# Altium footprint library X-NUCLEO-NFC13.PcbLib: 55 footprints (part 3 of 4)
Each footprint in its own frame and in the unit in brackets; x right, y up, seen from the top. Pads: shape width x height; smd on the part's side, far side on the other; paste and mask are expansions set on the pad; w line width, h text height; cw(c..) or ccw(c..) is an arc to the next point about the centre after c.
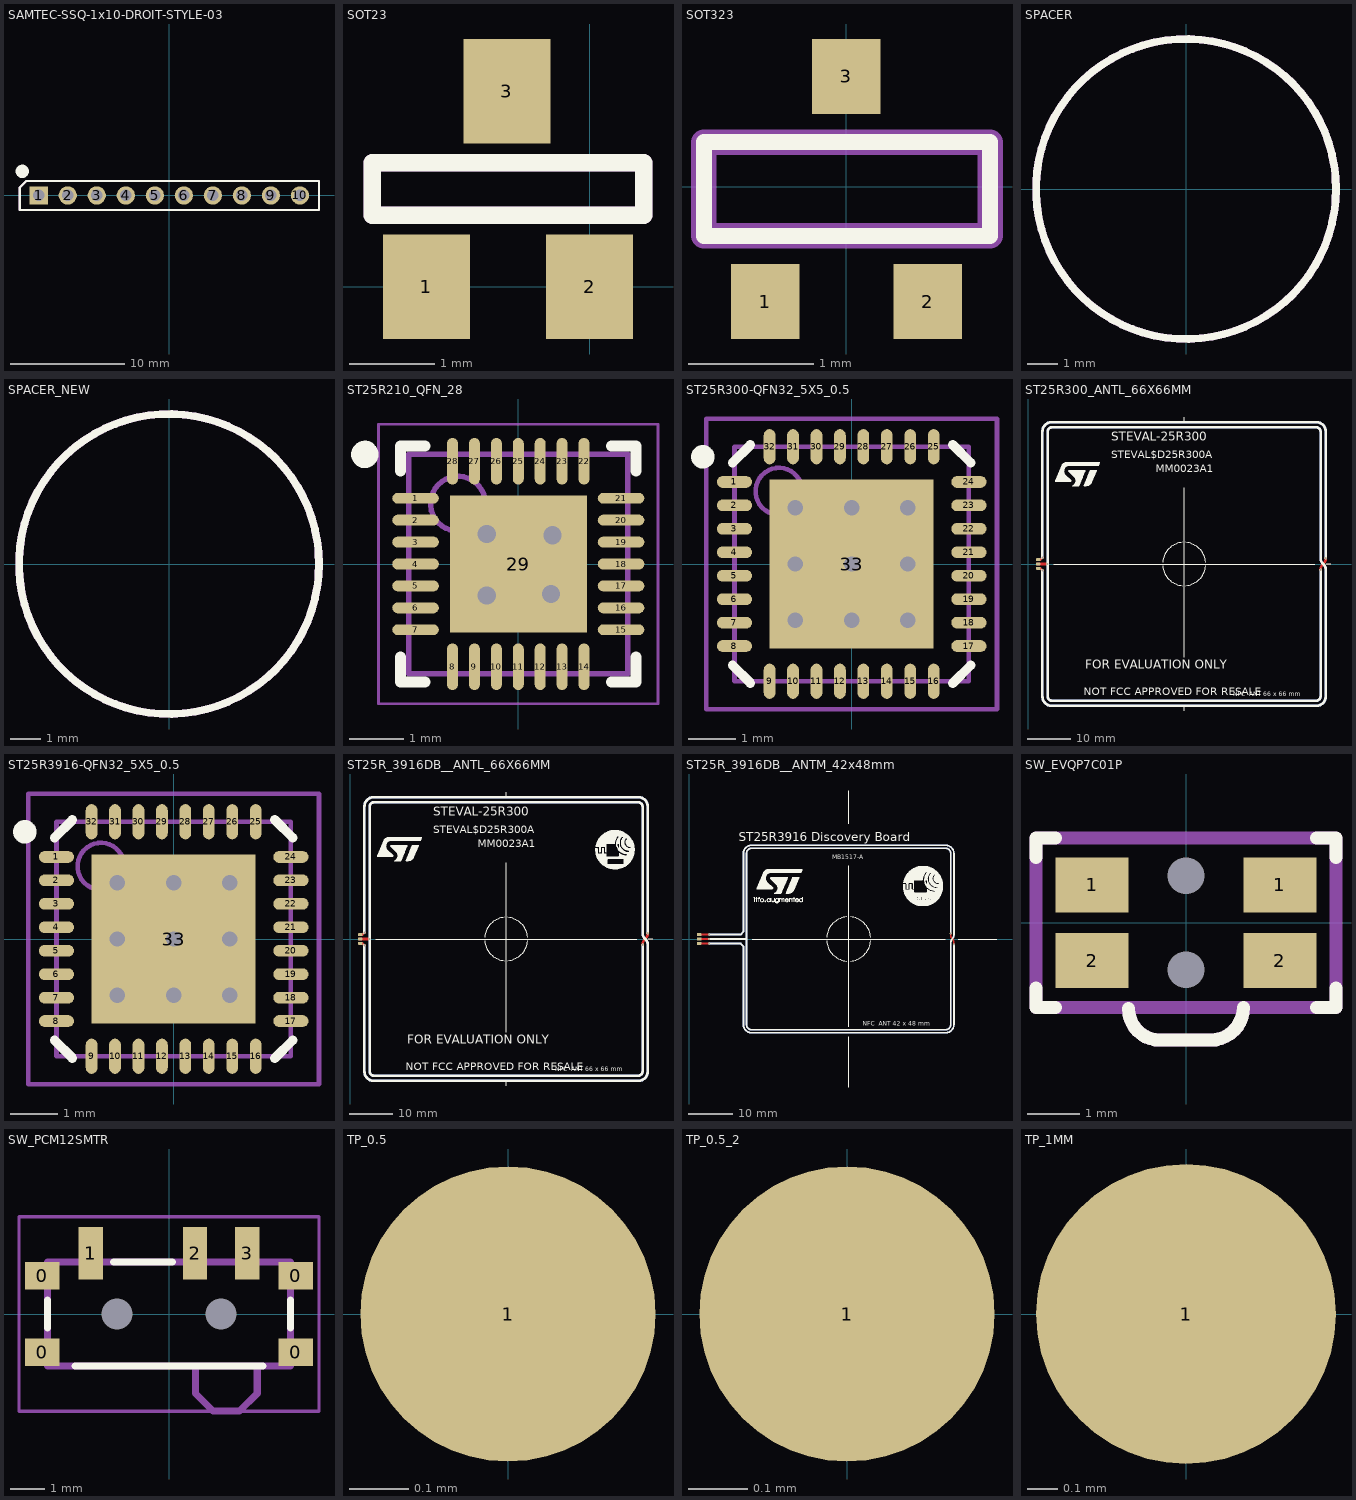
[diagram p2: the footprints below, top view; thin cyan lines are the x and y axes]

## SAMTEC-SSQ-1x10-DROIT-STYLE-03 [mm]
pads (10):
  rect 1.6x1.6 hole 1: 1(-11.43,0)
  round 1.6 hole 1: 2(-8.89,0) 3(-6.35,0) 4(-3.81,0) 5(-1.27,0) 6(1.27,0) 7(3.81,0) 8(6.35,0) 9(8.89,0) 10(11.43,0)
Top Overlay:
  circle w0.6: c-12.874,2.11 r0.284
  lines w0.2: -13.1,-1.27 13.1,-1.27 13.1,1.27 -12.53,1.27 -13.1,0.7 -13.1,-1.27
Top Assembly:
  lines w0.2: -13.1,-1.27 13.1,-1.27 13.1,1.27 -12.53,1.27 -13.1,0.7 -13.1,-1.27
  text "1" at -11.274,0.46 h1.05
  text ".Designator" at 3.976,2.71 h1.05
3D body "SSQ-110-03-L-S.stp": height 8.51, standoff -10.01, extent -12.954,-1.207 12.954,1.206

## SOT23 [mil]
pads (3):
  rect 40x48 smd paste+0 mask+0: 1(-75,0) 2(0,0) 3(-38,90)
Top Overlay:
  lines w8: -100,32.87 25,32.87 25,57.13 -100,57.13 -100,32.87
Top Assembly:
  lines w8: -100,32.87 25,32.87 25,57.13 -100,57.13 -100,32.87
  text ".Designator" at -105.54,66.46 h23.62
3D body: height 7.87, standoff 0, extent -45.28,62.99 -29.53,106.3
3D body: height 7.87, standoff 0, extent -82.68,-15.75 -66.93,27.56
3D body: height 7.87, standoff 0, extent -7.87,-15.75 7.87,27.56
3D body: height 15.75, standoff 1.97, extent -98.43,27.56 23.62,62.99

## SOT323 [mm]
pads (3):
  rect 0.55x0.6 smd paste+0 mask+0: 1(-0.65,-0.919) 2(0.65,-0.919) 3(0,0.881)
Top Overlay:
  lines w0.127: -1.14,-0.394 1.15,-0.394 1.15,0.356 -1.14,0.356 -1.14,-0.394
Top Assembly:
  lines w0.203: -1.14,-0.394 1.15,-0.394 1.15,0.356 -1.14,0.356 -1.14,-0.394
  text ".Designator" at -1.431,0.688 h0.6
3D body: height 0.2, standoff 0, extent -0.15,0.381 0.15,1.131
3D body: height 0.2, standoff 0, extent 0.45,-1.169 0.85,-0.419
3D body: height 0.2, standoff 0, extent -0.85,-1.169 -0.45,-0.394
3D body: height 0.4, standoff 0.05, extent -1.1,-0.494 1.05,0.406

## SPACER [mm] "spacer d5mmx4mm"
height 4
Top Overlay:
  circle w0.254: c0,0 r5
Top Assembly:
  circle w0.254: c0,0 r5
  text ".Designator" at -2.703,-0.326 h0.6

## SPACER_NEW [mm] "spacer d5mmx4mm"
height 4
Top Overlay:
  circle w0.254: c0,0 r5
Top Assembly:
  circle w0.254: c0,0 r5
  text ".Designator" at -2.703,-0.326 h0.6
3D body "SJxx03.stp": height 5.08, standoff 0, extent -5.561,-5.535 5.603,5.635

## ST25R210_QFN_28 [mm] "QFN, 28-Leads, Body 3,95x3,95mm, Pitch 0,40mm, Thermal Pad 2,50x2,50mm, IPC Medium Density"
height 0.55
pads (29):
  oval 0.85x0.2 smd: 1(-1.875,1.2) 2(-1.875,0.8) 3(-1.875,0.4) 4(-1.875,0) 5(-1.875,-0.4) 6(-1.875,-0.8) 7(-1.875,-1.2) 15(1.875,-1.2) 16(1.875,-0.8) 17(1.875,-0.4) 18(1.875,0) 19(1.875,0.4) 20(1.875,0.8) 21(1.875,1.2)
  oval 0.2x0.85 smd: 8(-1.2,-1.875) 9(-0.8,-1.875) 10(-0.4,-1.875) 11(0,-1.875) 12(0.4,-1.875) 13(0.8,-1.875) 14(1.2,-1.875) 22(1.2,1.875) 23(0.8,1.875) 24(0.4,1.875) 25(0,1.875) 26(-0.4,1.875) 27(-0.8,1.875) 28(-1.2,1.875)
  rect 2.5x2.5 smd: 29(0,0)
via -0.575,-0.575 diameter 0.66 hole 0.33
via 0.6,-0.55 diameter 0.66 hole 0.33
via 0.625,0.525 diameter 0.66 hole 0.33
via -0.575,0.55 diameter 0.66 hole 0.33
Top Overlay:
  circle w0.25: c-2.8,2 r0.125
  lines w0.2: -2.15,-1.7 -2.15,-2.15 -1.7,-2.15 ; -2.15,1.7 -2.15,2.15 -1.7,2.15 ; 1.7,-2.15 2.15,-2.15 2.15,-1.7 ; 1.7,2.15 2.15,2.15 2.15,1.7
Top Assembly:
  circle w0.1: c-1.1,1.1 r0.5
  lines w0.1: -2,-2 2,-2 2,2 -2,2 -2,-2
Top Courtyard:
  lines w0.05: -2.55,-2.55 2.55,-2.55 2.55,2.55 -2.55,2.55 -2.55,-2.55
  lines w0.1: -0.5,0 0.5,0 ; 0,-0.5 0,0.5
3D body "QFN40P395X395X55_HS-29N.step": height 0.55, standoff 0, extent -2.01,-2.01 2.01,2.01

## ST25R300-QFN32_5X5_0.5 [mm]
height 0.5
pads (33):
  oval 0.75x0.25 smd mask+0.05: 1(-2.5,1.75) 2(-2.5,1.25) 3(-2.5,0.75) 4(-2.5,0.25) 5(-2.5,-0.25) 6(-2.5,-0.75) 7(-2.5,-1.25) 8(-2.5,-1.75) 17(2.5,-1.75) 18(2.5,-1.25) 19(2.5,-0.75) 20(2.5,-0.25) 21(2.5,0.25) 22(2.5,0.75) 23(2.5,1.25) 24(2.5,1.75)
  oval 0.25x0.75 smd mask+0.05: 9(-1.75,-2.5) 10(-1.25,-2.5) 11(-0.75,-2.5) 12(-0.25,-2.5) 13(0.25,-2.5) 14(0.75,-2.5) 15(1.25,-2.5) 16(1.75,-2.5) 25(1.75,2.5) 26(1.25,2.5) 27(0.75,2.5) 28(0.25,2.5) 29(-0.25,2.5) 30(-0.75,2.5) 31(-1.25,2.5) 32(-1.75,2.5)
  rect 3.5x3.6 smd paste-10 mask+0.05: 33(0,0)
via -1.2,-1.2 diameter 0.66 hole 0.33
via 1.2,-1.2 diameter 0.66 hole 0.33
via 0,-1.2 diameter 0.66 hole 0.33
via 1.2,0 diameter 0.66 hole 0.33
via 0,0 diameter 0.66 hole 0.33
via -1.2,0 diameter 0.66 hole 0.33
via 1.2,1.2 diameter 0.66 hole 0.33
via 0,1.2 diameter 0.66 hole 0.33
via -1.2,1.2 diameter 0.66 hole 0.33
Top Overlay:
  circle w0.25: c-3.173,2.286 r0.125
  lines w0.2: -2.54,-2.159 -2.159,-2.54 ; -2.54,2.159 -2.159,2.54 ; 2.159,-2.54 2.54,-2.159 ; 2.159,2.54 2.54,2.159
Top Paste:
  rectangle: -1.016,0.179 -0.178,1.017
  rectangle: 0.177,0.178 1.015,1.016
  rectangle: 0.178,-1.017 1.016,-0.179
  rectangle: -1.016,-1.015 -0.178,-0.177
  rectangle: 0.179,1.372 1.017,1.753
  rectangle: -1.015,1.372 -0.177,1.753
  rectangle: -1.04,-1.753 -0.202,-1.372
  rectangle: 0.179,-1.753 1.017,-1.372
  region: 1.727,0.179 1.727,1.017 1.346,1.017 1.346,0.179
  region: 1.726,-1.016 1.726,-0.178 1.345,-0.178 1.345,-1.016
  region: -1.346,-1.015 -1.346,-0.177 -1.727,-0.177 -1.727,-1.015
  region: -1.346,0.179 -1.346,1.017 -1.727,1.017 -1.727,0.179
Top Assembly:
  circle w0.1: c-1.55,1.55 r0.5
  lines w0.1: -2.5,-2.5 2.5,-2.5 2.5,2.5 -2.5,2.5 -2.5,-2.5
  text ".Designator" at -2.203,-1.326 h0.6
Top Courtyard:
  lines w0.1: -0.5,0 0.5,0 ; 0,-0.5 0,0.5 ; -3.1,-3.1 3.1,-3.1 3.1,3.1 -3.1,3.1 -3.1,-3.1
3D body "ST25R3916-QFN32-5.STEP": height 0.85, standoff 0, extent -2.501,-2.501 2.501,2.501

## ST25R300_ANTL_66X66MM [mm] "66mm x 66mm"
pads (3):
  rrect50% 1x0.7 smd: 1(2.275,-1) 2(2.275,1) 3(2.275,0)
via 68.65,1.334 diameter 0.6 hole 0.3
via 67.45,-1.334 diameter 0.6 hole 0.3
via 4.45,0 diameter 0.5 hole 0.2
via 3.25,1.45 diameter 0.5 hole 0.2
via 3.25,-1.45 diameter 0.5 hole 0.2
Top Layer:
  lines w0.6: 2.275,-1 2.8,-1 3.25,-1.45 ; 2.275,0 4.45,0 ; 2.275,1 2.8,1 3.25,1.45 ; 67.45,-1.334 cw(c69.223,-1.334) 67.969,-0.081 68.131,0.081 ccw(c66.877,1.334) 68.65,1.334
Bottom Layer:
  lines w0.6: 3.25,-1.45 3.25,-30.525 ccw(c5.475,-30.525) 5.475,-32.75 ; 3.25,1.45 3.25,30.525 cw(c5.475,30.525) 5.475,32.75 ; 67.45,-1.334 cw(c67.445,-1.339) 67.452,-1.339 67.452,-30.526 cw(c66.428,-30.526) 66.428,-31.55 5.474,-31.55 cw(c5.474,-30.526) 4.45,-30.526 4.45,30.526 cw(c5.474,30.526) 5.474,31.55 66.428,31.55 cw(c66.428,30.526) 67.452,30.526 67.452,1.334 ccw(c69.23,1.334) 67.973,0.077 68.131,-0.081 cw(c66.877,-1.334) 68.65,-1.334 68.65,-30.525 ; 68.65,1.334 68.65,30.525 ; 68.652,-30.525 cw(c66.427,-30.525) 66.427,-32.75 5.475,-32.75 ; 68.652,30.525 ccw(c66.427,30.525) 66.427,32.75 5.475,32.75 ; 5.475,-32.75 5.475,-32.75 ; 5.475,32.75 5.475,32.75
Top Overlay:
  drawing of 419 lines, arcs and shapes, not listed
  text "STEVAL-25R300" at 19.123,27.726 h3.5
  text "NFC  ANT 66 x 66 mm" at 47.275,-30.5 h1
  text "MM0023A1" at 29.402,20.585 h3
  text "STEVAL$D25R300A" at 19.133,23.821 h3
  text "FOR EVALUATION ONLY" at 13.147,-24.825 h3.5
  text "NOT FCC APPROVED FOR RESALE" at 12.829,-30.871 h3
Bottom Overlay:
  lines w0.2: 5.85,0 66.05,0 ; 30.969,-0.436 ccw(c35.95,0) 35.514,-4.981 ; 30.969,0.436 cw(c35.95,0) 35.514,4.981 ; 35.929,-21.525 35.949,17.57 ; 35.95,-33.85 35.95,-32.825 ; 35.95,32.825 35.95,33.85 ; 36.386,-4.981 ccw(c35.95,0) 40.931,-0.436 ; 36.386,4.981 cw(c35.95,0) 40.931,0.436 ; 68.725,0.05 69.75,0.05
  lines w0.6: 3.25,-1.45 3.25,-30.525 ccw(c5.475,-30.525) 5.475,-32.75 ; 3.25,1.45 3.25,30.525 cw(c5.475,30.525) 5.475,32.75 ; 67.45,-1.334 cw(c67.445,-1.339) 67.452,-1.339 67.452,-30.526 cw(c66.428,-30.526) 66.428,-31.55 5.474,-31.55 cw(c5.474,-30.526) 4.45,-30.526 4.45,30.526 cw(c5.474,30.526) 5.474,31.55 66.428,31.55 cw(c66.428,30.526) 67.452,30.526 67.452,1.334 ccw(c69.23,1.334) 67.973,0.077 68.131,-0.081 cw(c66.877,-1.334) 68.65,-1.334 68.65,-30.525 ; 68.65,1.334 68.65,30.525 ; 68.652,-30.525 cw(c66.427,-30.525) 66.427,-32.75 5.475,-32.75 ; 68.652,30.525 ccw(c66.427,30.525) 66.427,32.75 5.475,32.75 ; 5.475,-32.75 5.475,-32.75 ; 5.475,32.75 5.475,32.75 ; 3.25,2 ccw(c3.25,2) 3.25,2

## ST25R3916-QFN32_5X5_0.5 [mm]
height 0.5
pads (33):
  oval 0.75x0.25 smd mask+0.05: 1(-2.5,1.75) 2(-2.5,1.25) 3(-2.5,0.75) 4(-2.5,0.25) 5(-2.5,-0.25) 6(-2.5,-0.75) 7(-2.5,-1.25) 8(-2.5,-1.75) 17(2.5,-1.75) 18(2.5,-1.25) 19(2.5,-0.75) 20(2.5,-0.25) 21(2.5,0.25) 22(2.5,0.75) 23(2.5,1.25) 24(2.5,1.75)
  oval 0.25x0.75 smd mask+0.05: 9(-1.75,-2.5) 10(-1.25,-2.5) 11(-0.75,-2.5) 12(-0.25,-2.5) 13(0.25,-2.5) 14(0.75,-2.5) 15(1.25,-2.5) 16(1.75,-2.5) 25(1.75,2.5) 26(1.25,2.5) 27(0.75,2.5) 28(0.25,2.5) 29(-0.25,2.5) 30(-0.75,2.5) 31(-1.25,2.5) 32(-1.75,2.5)
  rect 3.5x3.6 smd paste-10 mask+0.05: 33(0,0)
via -1.2,1.2 diameter 0.66 hole 0.33
via 0,1.2 diameter 0.66 hole 0.33
via 1.2,1.2 diameter 0.66 hole 0.33
via -1.2,0 diameter 0.66 hole 0.33
via 0,0 diameter 0.66 hole 0.33
via 1.2,0 diameter 0.66 hole 0.33
via 0,-1.2 diameter 0.66 hole 0.33
via 1.2,-1.2 diameter 0.66 hole 0.33
via -1.2,-1.2 diameter 0.66 hole 0.33
Top Overlay:
  circle w0.25: c-3.173,2.286 r0.125
  lines w0.2: -2.54,-2.159 -2.159,-2.54 ; -2.54,2.159 -2.159,2.54 ; 2.159,-2.54 2.54,-2.159 ; 2.159,2.54 2.54,2.159
Top Paste:
  region: -1.346,0.179 -1.346,1.017 -1.727,1.017 -1.727,0.179
  region: -1.346,-1.015 -1.346,-0.177 -1.727,-0.177 -1.727,-1.015
  region: 1.726,-1.016 1.726,-0.178 1.345,-0.178 1.345,-1.016
  region: 1.727,0.179 1.727,1.017 1.346,1.017 1.346,0.179
  rectangle: 0.179,-1.753 1.017,-1.372
  rectangle: -1.04,-1.753 -0.202,-1.372
  rectangle: -1.015,1.372 -0.177,1.753
  rectangle: 0.179,1.372 1.017,1.753
  rectangle: -1.016,-1.015 -0.178,-0.177
  rectangle: 0.178,-1.017 1.016,-0.179
  rectangle: 0.177,0.178 1.015,1.016
  rectangle: -1.016,0.179 -0.178,1.017
Top Assembly:
  circle w0.1: c-1.55,1.55 r0.5
  lines w0.1: -2.5,-2.5 -2.5,2.5 2.5,2.5 2.5,-2.5 -2.5,-2.5
  text ".Designator" at -2.203,-1.326 h0.6
Top Courtyard:
  lines w0.1: -0.5,0 0.5,0 ; 0,-0.5 0,0.5 ; -3.1,-3.1 -3.1,3.1 3.1,3.1 3.1,-3.1 -3.1,-3.1
3D body "ST25R3916-QFN32-5.STEP": height 0.85, standoff 0, extent -2.501,-2.501 2.501,2.501

## ST25R_3916DB__ANTL_66X66MM [mm] "66mm x 66mm"
pads (3):
  rrect50% 1x0.7 smd: 1(2.275,-1) 2(2.275,1) 3(2.275,0)
via 3.25,-1.45 diameter 0.5 hole 0.2
via 3.25,1.45 diameter 0.5 hole 0.2
via 4.45,0 diameter 0.5 hole 0.2
via 67.45,-1.334 diameter 0.6 hole 0.3
via 68.65,1.334 diameter 0.6 hole 0.3
Top Layer:
  lines w0.6: 2.275,-1 2.8,-1 3.25,-1.45 ; 2.275,0 4.45,0 ; 2.275,1 2.8,1 3.25,1.45 ; 67.45,-1.334 cw(c69.223,-1.334) 67.969,-0.081 68.131,0.081 ccw(c66.877,1.334) 68.65,1.334
Bottom Layer:
  lines w0.6: 3.25,-1.45 3.25,-30.525 ccw(c5.475,-30.525) 5.475,-32.75 ; 3.25,1.45 3.25,30.525 cw(c5.475,30.525) 5.475,32.75 ; 67.45,-1.334 cw(c67.445,-1.339) 67.452,-1.339 67.452,-30.526 cw(c66.428,-30.526) 66.428,-31.55 5.474,-31.55 cw(c5.474,-30.526) 4.45,-30.526 4.45,30.526 cw(c5.474,30.526) 5.474,31.55 66.428,31.55 cw(c66.428,30.526) 67.452,30.526 67.452,1.334 ccw(c69.23,1.334) 67.973,0.077 68.131,-0.081 cw(c66.877,-1.334) 68.65,-1.334 68.65,-30.525 ; 68.65,1.334 68.65,30.525 ; 68.652,-30.525 cw(c66.427,-30.525) 66.427,-32.75 5.475,-32.75 ; 68.652,30.525 ccw(c66.427,30.525) 66.427,32.75 5.475,32.75 ; 5.475,-32.75 5.475,-32.75 ; 5.475,32.75 5.475,32.75
Top Overlay:
  drawing of 426 lines, arcs and shapes, not listed
  text "NOT FCC APPROVED FOR RESALE" at 12.829,-30.871 h3
  text "FOR EVALUATION ONLY" at 13.147,-24.825 h3.5
  text "STEVAL$D25R300A" at 19.133,23.821 h3
  text "MM0023A1" at 29.402,20.585 h3
  text "NFC  ANT 66 x 66 mm" at 47.275,-30.5 h1
  text "STEVAL-25R300" at 19.123,27.726 h3.5
Bottom Overlay:
  lines w0.2: 5.85,0 66.05,0 ; 30.969,-0.436 ccw(c35.95,0) 35.514,-4.981 ; 30.969,0.436 cw(c35.95,0) 35.514,4.981 ; 35.929,-21.525 35.949,17.57 ; 35.95,-33.85 35.95,-32.825 ; 35.95,32.825 35.95,33.85 ; 36.386,-4.981 ccw(c35.95,0) 40.931,-0.436 ; 36.386,4.981 cw(c35.95,0) 40.931,0.436 ; 68.725,0.05 69.75,0.05
  lines w0.6: 3.25,-1.45 3.25,-30.525 ccw(c5.475,-30.525) 5.475,-32.75 ; 3.25,1.45 3.25,30.525 cw(c5.475,30.525) 5.475,32.75 ; 67.45,-1.334 cw(c67.445,-1.339) 67.452,-1.339 67.452,-30.526 cw(c66.428,-30.526) 66.428,-31.55 5.474,-31.55 cw(c5.474,-30.526) 4.45,-30.526 4.45,30.526 cw(c5.474,30.526) 5.474,31.55 66.428,31.55 cw(c66.428,30.526) 67.452,30.526 67.452,1.334 ccw(c69.23,1.334) 67.973,0.077 68.131,-0.081 cw(c66.877,-1.334) 68.65,-1.334 68.65,-30.525 ; 68.65,1.334 68.65,30.525 ; 68.652,-30.525 cw(c66.427,-30.525) 66.427,-32.75 5.475,-32.75 ; 68.652,30.525 ccw(c66.427,30.525) 66.427,32.75 5.475,32.75 ; 5.475,-32.75 5.475,-32.75 ; 5.475,32.75 5.475,32.75 ; 3.25,2 ccw(c3.25,2) 3.25,2

## ST25R_3916DB__ANTM_42x48mm [mm] "42mm x 48mm"
pads (3):
  rrect50% 1x0.7 smd: 1(2.275,-1) 2(2.275,1) 3(2.275,0)
via 4.45,1 diameter 0.5 hole 0.2
via 4.45,0 diameter 0.5 hole 0.2
via 4.45,-1 diameter 0.5 hole 0.2
via 59.681,-1.25 diameter 0.5 hole 0.2
via 58.983,1.25 diameter 0.5 hole 0.2
Top Layer:
  lines w0.4: 2.275,-1 4.5,-1 ; 2.275,0 4.45,0 ; 2.275,1 4.5,1 ; 58.983,1.25 58.983,0.859 ccw(c60.199,0.859) 59.339,0 cw(c58.527,-0.812) 59.675,-0.812 59.675,-1.25
Bottom Layer:
  lines w0.4: 4.45,-1 11.603,-1 11.781,-1.178 12.231,-1.628 12.231,-19.372 ; 4.45,0 12.928,0 ; 4.45,1 11.603,1 12.231,1.628 ; 12.228,-19.28 ccw(c14.098,-19.28) 14.098,-21.15 57.811,-21.15 ccw(c57.811,-19.28) 59.681,-19.28 59.681,-1.25 ; 12.231,2.325 12.231,1.628 ; 12.231,19.273 cw(c14.101,19.273) 14.101,21.143 57.811,21.143 cw(c57.811,19.273) 59.681,19.273 ; 12.231,19.298 12.231,1.628 ; 12.928,19.277 cw(c14.098,19.277) 14.098,20.447 ; 12.928,19.299 12.928,-19.277 ccw(c14.098,-19.277) 14.098,-20.447 57.794,-20.447 ; 14.101,20.448 57.811,20.448 cw(c57.811,19.278) 58.981,19.278 ; 57.819,-20.447 ccw(c57.819,-19.277) 58.989,-19.277 58.989,-1.25 58.989,-0.812 cw(c60.137,-0.812) 59.325,0 ccw(c58.466,0.859) 59.681,0.859 59.681,1.25 59.681,19.278 ; 58.983,1.25 58.983,19.253
Top Overlay:
  drawing of 2857 lines, arcs and shapes, not listed
  text "ST25R3916 Discovery Board" at 11.2,22.05 h2
  text "MB1517-A" at 32.285,17.925 h1
  text "NFC  ANT 42 x 48 mm" at 39.175,-19.5 h1
Bottom Overlay:
  lines w0.2: 5,0 10.9,0 ; 14.2,0 57.7,0 ; 30.969,-0.436 ccw(c35.95,0) 35.514,-4.981 ; 30.969,0.436 cw(c35.95,0) 35.514,4.981 ; 35.95,-33.425 35.95,-22 ; 35.95,-19.75 35.95,19.75 ; 35.95,22 35.95,33.425 ; 36.386,-4.981 ccw(c35.95,0) 40.931,-0.436 ; 36.386,4.981 cw(c35.95,0) 40.931,0.436 ; 60.65,0 69.4,0
  lines w0.4: 4.45,-1 11.603,-1 11.781,-1.178 12.231,-1.628 12.231,-19.372 ; 4.45,0 12.928,0 ; 4.45,1 11.603,1 12.231,1.628 ; 12.228,-19.28 ccw(c14.098,-19.28) 14.098,-21.15 57.811,-21.15 ccw(c57.811,-19.28) 59.681,-19.28 59.681,-1.25 ; 12.231,2.325 12.231,1.628 ; 12.231,19.273 cw(c14.101,19.273) 14.101,21.143 57.811,21.143 cw(c57.811,19.273) 59.681,19.273 ; 12.231,19.298 12.231,1.628 ; 12.928,19.277 cw(c14.098,19.277) 14.098,20.447 ; 12.928,19.299 12.928,-19.277 ccw(c14.098,-19.277) 14.098,-20.447 57.794,-20.447 ; 14.101,20.448 57.811,20.448 cw(c57.811,19.278) 58.981,19.278 ; 57.819,-20.447 ccw(c57.819,-19.277) 58.989,-19.277 58.989,-1.25 58.989,-0.812 cw(c60.137,-0.812) 59.325,0 ccw(c58.466,0.859) 59.681,0.859 59.681,1.25 59.681,19.278 ; 58.983,1.25 58.983,19.253

## SW_EVQP7C01P [mm]
height 1.35
pads (6):
  round 0 hole 0.7 unplated mask+0: 0(0,-0.9) 0(0,0.9)
  rect 1.4x1.05 smd paste+0 mask+0: 1(-1.8,0.725) 1(1.8,0.725) 2(-1.8,-0.725) 2(1.8,-0.725)
Top Overlay:
  lines w0.254: -2.875,-1.25 -2.875,-1.625 -2.5,-1.625 ; -2.875,1.25 -2.875,1.625 -2.5,1.625 ; -1.1,-1.65 ccw(c-0.5,-1.65) -0.5,-2.25 0.475,-2.25 ccw(c0.475,-1.625) 1.1,-1.625 ; 2.5,-1.625 2.875,-1.625 2.875,-1.25 ; 2.5,1.625 2.875,1.625 2.875,1.25
Top 3D Body:
  lines w0.254: -1.1,-1.65 ccw(c-0.5,-1.65) -0.5,-2.25 0.475,-2.25 ccw(c0.475,-1.625) 1.1,-1.625 ; -2.875,-1.625 2.875,-1.625 2.875,1.625 -2.875,1.625 -2.875,-1.625
3D body "EVQ-P7L01P.step": height 1.35, standoff -0.5, extent -2.355,-2.09 2.345,1.46

## SW_PCM12SMTR [mm]
pads (9):
  rect 1x0.8 smd paste+0 mask+0: 0(-3.65,-1.1) 0(-3.65,1.1) 0(3.65,-1.1) 0(3.65,1.1)
  round 0 hole 0.9 unplated mask+0: 0(-1.5,0) 0(1.5,0)
  rect 0.7x1.5 smd paste+0 mask+0: 1(-2.25,1.75) 2(0.75,1.75) 3(2.25,1.75)
Top Overlay:
  lines w0.2: -3.5,-0.4 -3.5,0.4 ; -2.7,-1.5 2.7,-1.5 ; -1.6,1.5 0.1,1.5 ; 3.5,-0.4 3.5,0.4
Top Assembly:
  lines w0.2: -3.5,-1.5 3.5,-1.5 3.5,1.5 -3.5,1.5 -3.5,-1.5
  lines w0.203: 0.762,-1.524 0.762,-2.286 1.27,-2.794 2.032,-2.794 2.54,-2.286 2.54,-1.524
  text ".Designator" at -3.1,-0.2 h0.8
Top Courtyard:
  lines w0.1: -4.318,-2.794 -4.318,2.794 4.318,2.794 4.318,-2.794 -4.318,-2.794
3D body "Switch_slide_pcm12smtr.stp": height 1.4, standoff -0.5, extent -3.85,-2.8 3.85,2.2

## TP_0.5 [mm] "Test Point 0.5mm"
pads (1):
  round 0.5 smd: 1(0,0)
Top Assembly:
  text ".Designator" at -0.953,0.424 h0.6

## TP_0.5_2 [mm]
pads (1):
  round 0.5 smd: 1(0,0)
Top Assembly:
  text ".Designator" at -0.953,0.424 h0.6

## TP_1MM [mm] "Test Point 1mm"
pads (1):
  round 1 smd: 1(0,0)
Top Assembly:
  text ".Designator" at -0.953,0.674 h0.6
